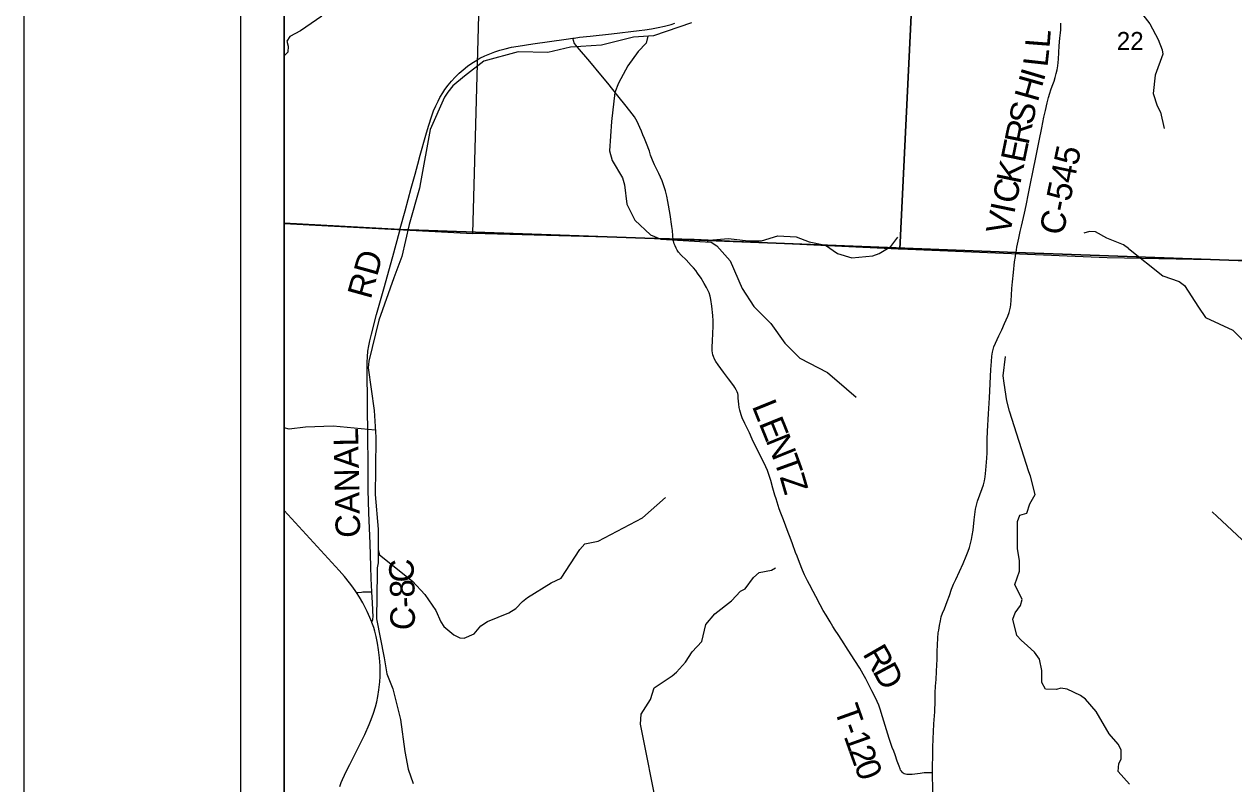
# Model space of a CAD drawing. Extents: x 0 to 34, y 0 to 22.
# Drawn here: x 2 to 4.796, y 15.243 to 16.998 of the extents above; entities that cross this region are included whole.
import ezdxf

# ---------------------------------------------------------------- set-up
doc = ezdxf.new("R2010")
doc.units = 0
for name, color, linetype in [('GM_X_County', 7, 'Continuous'), ('GM_X_County_Road', 7, 'Continuous'), ('GM_X_County_Road_Text', 7, 'Continuous'), ('GM_X_Minor_River', 7, 'Continuous'), ('GM_X_Section', 7, 'Continuous'), ('GM_X_Section_Text', 7, 'Continuous'), ('GM_X_State_Route', 7, 'Continuous'), ('GM_X_Township', 7, 'Continuous'), ('GM_X_Township_Road', 7, 'Continuous'), ('GM_X_Township_Road_Text', 7, 'Continuous'), ('SH_Border', 7, 'Continuous'), ('SH_Data', 7, 'Continuous')]:
    doc.layers.add(name, color=color, linetype=linetype)

msp = doc.modelspace()

# ---------------------------------------------------------------- linework, layer by layer
at = {"layer": 'GM_X_County'}
msp.add_lwpolyline([(7.0736, 21.2003), (2.6013, 21.2003), (2.6013, 14.4003), (9.4013, 14.4003), (9.4013, 21.1598)], dxfattribs=at)
at = {"layer": 'GM_X_County_Road'}
for points in [[(3.2681, 16.9653), (3.271, 16.9657), (3.2838, 16.9674), (3.3083, 16.97), (3.3577, 16.9753), (3.4214, 16.9828), (3.4348, 16.9846), (3.4501, 16.9869), (3.4653, 16.9899), (3.4804, 16.9933), (3.4954, 16.9974), (3.5042, 17.0002)], [(4.2927, 16.4699), (4.2928, 16.4705), (4.2949, 16.4826), (4.2991, 16.5037), (4.3023, 16.5188), (4.3052, 16.5309), (4.3122, 16.5611), (4.3161, 16.5793), (4.3216, 16.6067), (4.3248, 16.6219), (4.3273, 16.634), (4.331, 16.6523), (4.3403, 16.6979), (4.3463, 16.7284), (4.3525, 16.7587), (4.3574, 16.783), (4.3606, 16.7981), (4.3648, 16.8162), (4.3681, 16.8288), (4.3709, 16.8384), (4.3734, 16.8463), (4.3762, 16.8544), (4.3806, 16.8659), (4.3835, 16.8746), (4.3859, 16.8835), (4.3878, 16.8926), (4.3892, 16.9018), (4.3908, 16.9173), (4.3919, 16.9327), (4.3929, 16.9481), (4.3943, 16.9652), (4.3956, 16.9779), (4.3964, 16.9848), (4.3964, 16.994), (4.396, 17.0002)], [(2.8695, 16.5261), (2.8805, 16.5665), (2.8949, 16.6187), (2.9036, 16.6515), (2.91, 16.6745), (2.9157, 16.6949), (2.9283, 16.7411), (2.9345, 16.7621), (2.9421, 16.7858), (2.9464, 16.7975), (2.9512, 16.809), (2.9566, 16.8203), (2.961, 16.8285), (2.9674, 16.8392), (2.9726, 16.847), (2.9801, 16.8569), (2.9881, 16.8665), (2.9966, 16.8756), (3.0055, 16.8843), (3.0148, 16.8926), (3.0246, 16.9005), (3.0347, 16.9077), (3.0426, 16.9127), (3.0535, 16.9189), (3.0647, 16.9244), (3.0761, 16.9293), (3.0877, 16.9338), (3.0996, 16.9377), (3.1116, 16.9409), (3.1268, 16.9443), (3.1421, 16.9471), (3.1759, 16.9522), (3.2528, 16.9632), (3.2681, 16.9653)], [(2.8036, 15.6871), (2.8021, 15.7174), (2.8011, 15.7453), (2.7994, 15.7981), (2.7964, 15.8695), (2.7955, 15.9223), (2.7951, 15.9844), (2.7947, 16.0434), (2.7938, 16.1211), (2.7928, 16.1987), (2.7927, 16.2174), (2.7933, 16.2298), (2.7945, 16.2422), (2.7964, 16.2546), (2.7988, 16.2668), (2.8025, 16.2819), (2.8147, 16.3269), (2.8313, 16.3867), (2.8519, 16.4616), (2.8674, 16.5185), (2.8688, 16.5234), (2.8695, 16.5261)], [(4.1, 15.2685), (4.0999, 15.2892), (4.1002, 15.3016), (4.1008, 15.3264), (4.1014, 15.3481), (4.102, 15.3636), (4.1031, 15.3821), (4.1043, 15.4006), (4.1048, 15.4099), (4.1056, 15.4348), (4.1061, 15.4534), (4.1069, 15.4689), (4.108, 15.4844), (4.1092, 15.5029), (4.1101, 15.5183), (4.1105, 15.5307), (4.1105, 15.54), (4.1105, 15.5493), (4.1109, 15.5647), (4.1118, 15.5801), (4.113, 15.5924), (4.114, 15.5985), (4.1157, 15.6091), (4.1181, 15.6197), (4.1201, 15.6287), (4.1229, 15.6376), (4.1273, 15.6475), (4.1338, 15.6642), (4.1387, 15.6786), (4.1434, 15.6929), (4.1482, 15.7044), (4.1535, 15.7156), (4.1703, 15.7521), (4.1779, 15.769), (4.1824, 15.7806), (4.1854, 15.7894), (4.1879, 15.7984), (4.19, 15.8075), (4.1916, 15.8166), (4.1934, 15.8288), (4.1961, 15.8534), (4.1975, 15.8657), (4.1995, 15.878), (4.2015, 15.8871), (4.2041, 15.896), (4.2093, 15.9107), (4.2146, 15.9253), (4.2174, 15.9341), (4.2196, 15.9431), (4.2211, 15.9523), (4.2227, 15.9676), (4.2251, 15.9954), (4.2258, 16.0078), (4.2261, 16.0202), (4.2263, 16.0389), (4.227, 16.0575), (4.2293, 16.0978), (4.2315, 16.135), (4.2349, 16.2002), (4.2359, 16.2188), (4.2371, 16.2312), (4.2385, 16.2404), (4.24, 16.2464), (4.2418, 16.2523), (4.2454, 16.2609), (4.2531, 16.2779), (4.2597, 16.292), (4.2661, 16.3061), (4.2735, 16.3232), (4.2768, 16.3319), (4.2786, 16.3378), (4.28, 16.3439), (4.2809, 16.35), (4.2817, 16.3593), (4.2822, 16.3717), (4.283, 16.3872), (4.2845, 16.4027), (4.2867, 16.4243), (4.2896, 16.449), (4.2913, 16.4613), (4.2927, 16.4699)], [(2.7683, 15.685), (2.7722, 15.6855), (2.7797, 15.6863), (2.7826, 15.6864), (2.8036, 15.6871)], [(2.8038, 15.6168), (2.8057, 15.6225), (2.8061, 15.6252), (2.8065, 15.6279), (2.8049, 15.6616), (2.8036, 15.6871)], [(4.1243, 14.9987), (4.1248, 14.9996), (4.1258, 15.0026), (4.1261, 15.0056), (4.126, 15.0087), (4.1246, 15.0179), (4.1213, 15.0457), (4.1188, 15.0673), (4.1167, 15.0889), (4.1153, 15.1049), (4.1127, 15.1266), (4.1109, 15.1382), (4.106, 15.1626), (4.1034, 15.1779), (4.1023, 15.1872), (4.1013, 15.2027), (4.1008, 15.2213), (4.1004, 15.24), (4.1, 15.2555), (4.1, 15.2685)]]:
    msp.add_lwpolyline(points, dxfattribs=at)
at = {"layer": 'GM_X_Minor_River'}
for points in [[(4.5595, 17.1163), (4.5776, 17.0849), (4.5859, 17.0193), (4.6019, 16.9985), (4.621, 16.9625), (4.631, 16.9386), (4.6318, 16.9288), (4.6142, 16.8802), (4.6098, 16.8376), (4.6191, 16.8092), (4.6271, 16.7945), (4.6356, 16.7569)], [(2.6882, 17.0164), (2.6391, 16.9821), (2.6137, 16.9692), (2.6069, 16.9585), (2.6104, 16.9468), (2.6093, 16.9335), (2.6013, 16.9244)], [(3.5424, 17.0005), (3.455, 16.971), (3.4084, 16.9675), (3.3349, 16.949), (3.2629, 16.9443), (3.2107, 16.932), (3.1417, 16.934), (3.0626, 16.9122), (3.0176, 16.8779), (2.9911, 16.855), (2.9794, 16.841), (2.9715, 16.8292), (2.9388, 16.7544), (2.9165, 16.6321), (2.9142, 16.6189), (2.8899, 16.535), (2.8731, 16.4609), (2.8547, 16.4119), (2.8197, 16.3143), (2.7966, 16.2198), (2.7955, 16.2043), (2.8087, 16.1057), (2.8127, 16.0442), (2.8118, 15.9703), (2.8116, 15.9118), (2.8179, 15.8311), (2.8186, 15.7537), (2.8163, 15.7419), (2.816, 15.7305), (2.8141, 15.6243), (2.8318, 15.5341), (2.8384, 15.4977), (2.8521, 15.4624), (2.8702, 15.3919), (2.8803, 15.318), (2.8876, 15.2774), (2.8991, 15.2441)], [(3.4416, 16.97), (3.438, 16.9539), (3.4195, 16.9345), (3.3953, 16.9018), (3.3735, 16.8615), (3.3652, 16.8399), (3.3578, 16.7727), (3.3528, 16.7052), (3.3589, 16.6832), (3.3833, 16.6427), (3.3879, 16.6268), (3.3933, 16.5824), (3.4113, 16.5449), (3.4478, 16.5109), (3.472, 16.5015), (3.588, 16.4943), (3.6013, 16.486), (3.6317, 16.4512), (3.66, 16.3871), (3.6866, 16.3459), (3.7258, 16.3062), (3.7585, 16.2607), (3.7928, 16.2263), (3.8569, 16.1932), (3.9006, 16.1554), (3.923, 16.1365)], [(3.579, 16.4948), (3.5823, 16.4988), (3.6282, 16.5027), (3.6736, 16.4976), (3.7047, 16.4977), (3.7418, 16.5088), (3.7843, 16.5066), (3.8146, 16.495), (3.8525, 16.4875), (3.8803, 16.4682), (3.9129, 16.4581), (3.9614, 16.4624), (3.9765, 16.4682), (4.0037, 16.4846), (4.0196, 16.5058)], [(4.5528, 16.4798), (4.5411, 16.4885), (4.5024, 16.5039), (4.4762, 16.5179), (4.4629, 16.519), (4.4497, 16.5151)], [(4.5528, 16.4798), (4.6319, 16.4163), (4.6702, 16.4031), (4.682, 16.3945), (4.7149, 16.3445), (4.7309, 16.3203), (4.7939, 16.291), (4.8248, 16.2604), (4.8466, 16.2184), (4.861, 16.2086), (4.8857, 16.2011), (4.9465, 16.1737), (4.9669, 16.1764), (4.9973, 16.1637), (5.0125, 16.1512), (5.0372, 16.138), (5.0721, 16.1306), (5.1199, 16.1343)], [(4.555, 15.2428), (4.5288, 15.2716), (4.5302, 15.2905), (4.5355, 15.3004), (4.5358, 15.3216), (4.529, 15.3353), (4.5084, 15.3587), (4.4779, 15.4102), (4.4532, 15.4386), (4.4418, 15.4473), (4.4111, 15.4616), (4.3963, 15.4639), (4.3864, 15.4612), (4.361, 15.4622), (4.3523, 15.4774), (4.3522, 15.5047), (4.3468, 15.5312), (4.3357, 15.5471), (4.3194, 15.5619), (4.3046, 15.5751), (4.2947, 15.5857), (4.2851, 15.6236), (4.2907, 15.6384), (4.3028, 15.6551), (4.3073, 15.6692), (4.2901, 15.7036), (4.3006, 15.7348), (4.3006, 15.7594), (4.2959, 15.7864), (4.2965, 15.849), (4.3017, 15.8641), (4.318, 15.8684), (4.3244, 15.89), (4.3372, 15.9117), (4.3261, 15.9541), (4.3222, 15.964), (4.2778, 16.1038), (4.2713, 16.1277), (4.2655, 16.1686), (4.2632, 16.1857), (4.2683, 16.2301)], [(2.8116, 16.0601), (2.7141, 16.069), (2.65, 16.0669), (2.6125, 16.0626), (2.6013, 16.0656)], [(2.8183, 15.7837), (2.8215, 15.7723), (2.8979, 15.7114), (2.9264, 15.6804), (2.9516, 15.6433), (2.963, 15.6176), (2.9702, 15.6066), (2.9934, 15.5877), (3.0067, 15.5805), (3.0173, 15.5794), (3.04, 15.5901), (3.0555, 15.608), (3.071, 15.6179), (3.1202, 15.6385), (3.1368, 15.6481), (3.1519, 15.6641), (3.1633, 15.6736), (3.2181, 15.7079), (3.2412, 15.7182), (3.2842, 15.7843), (3.2959, 15.7973), (3.3269, 15.8035), (3.4294, 15.8573), (3.4823, 15.9048)], [(5.0759, 15.5103), (5.0739, 15.5171), (5.0628, 15.5292), (5.0407, 15.564), (4.9965, 15.612), (4.9273, 15.6497), (4.9063, 15.675), (4.8891, 15.7098), (4.8529, 15.7651), (4.8151, 15.8078), (4.7577, 15.8606), (4.7462, 15.8712)], [(3.4562, 15.2227), (3.4342, 15.3349), (3.4246, 15.3812), (3.426, 15.4039), (3.4475, 15.4381), (3.4561, 15.4647), (3.4981, 15.4929), (3.5079, 15.5009), (3.5287, 15.5245), (3.5441, 15.5481), (3.5664, 15.5717), (3.5754, 15.6111), (3.5969, 15.6359), (3.6347, 15.6663), (3.6558, 15.6884), (3.6664, 15.6934), (3.6861, 15.7196), (3.6993, 15.7314), (3.7273, 15.7368), (3.7371, 15.7418)]]:
    msp.add_lwpolyline(points, dxfattribs=at)
at = {"layer": 'GM_X_Section'}
msp.add_line((2.6013, 17.5659), (2.6013, 16.5373), dxfattribs=at)
msp.add_lwpolyline([(2.6013, 16.5373), (3.0372, 16.514), (3.0654, 17.5504), (2.6013, 17.5659)], dxfattribs=at)
for points in [[(3.0654, 17.5504), (4.0746, 17.5111), (4.0244, 16.4784), (4.0204, 16.4785), (3.5484, 16.5002), (3.0372, 16.514)], [(4.0746, 17.5111), (5.0805, 17.4591), (5.0528, 16.4469), (4.8222, 16.4519), (4.5034, 16.4581), (4.0244, 16.4784)]]:
    msp.add_lwpolyline(points, close=True, dxfattribs=at)
at = {"layer": 'GM_X_State_Route'}
msp.add_lwpolyline([(2.7297, 15.2375), (2.7331, 15.2464), (2.7359, 15.2532), (2.7451, 15.273), (2.7528, 15.288), (2.7793, 15.3407), (2.7876, 15.3574), (2.7977, 15.3801), (2.8024, 15.3916), (2.8076, 15.4062), (2.8121, 15.421), (2.8152, 15.433), (2.8177, 15.4451), (2.8201, 15.4605), (2.8221, 15.4789), (2.8227, 15.4915), (2.8229, 15.5037), (2.8227, 15.5159), (2.8214, 15.5346), (2.8192, 15.5531), (2.8167, 15.5684), (2.8138, 15.5836), (2.8109, 15.5957), (2.8083, 15.6046), (2.804, 15.6162), (2.8038, 15.6168), (2.7992, 15.6276), (2.7925, 15.6416), (2.7826, 15.661), (2.775, 15.6745), (2.7683, 15.685), (2.7667, 15.6876), (2.7597, 15.6978), (2.7523, 15.7078), (2.7406, 15.7222), (2.7284, 15.7364), (2.6013, 15.8744)], dxfattribs=at)
at = {"layer": 'GM_X_Township'}
for points in [[(6.2234, 21.2003), (2.6013, 21.2003), (2.6013, 16.5379)], [(2.6013, 16.5379), (2.8688, 16.5234), (3.5006, 16.5009), (4.2928, 16.4705), (5.2983, 16.434), (6.0664, 16.4042), (6.0778, 16.7443), (6.0911, 17.2548), (6.11, 17.7459), (6.1473, 18.845), (6.1717, 19.6397), (6.1731, 19.6616), (6.1731, 19.6818), (6.1733, 19.6859), (6.2234, 21.2003)], [(2.6013, 16.5379), (2.6013, 14.4003), (6.0009, 14.4003)], [(5.2983, 16.434), (4.2928, 16.4705), (3.5006, 16.5009), (2.8688, 16.5234), (2.6013, 16.5379)]]:
    msp.add_lwpolyline(points, dxfattribs=at)
at = {"layer": 'GM_X_Township_Road'}
for points in [[(3.4997, 16.5072), (3.4995, 16.5088), (3.4986, 16.5212), (3.4975, 16.5304), (3.493, 16.558), (3.4879, 16.5886), (3.4852, 16.6007), (3.4822, 16.6128), (3.4788, 16.6246), (3.4746, 16.6362), (3.471, 16.6448), (3.4671, 16.6532), (3.46, 16.667), (3.4573, 16.6726), (3.4547, 16.6782), (3.4522, 16.6839), (3.4479, 16.6955), (3.4453, 16.7044), (3.4389, 16.7219), (3.4341, 16.7334), (3.4304, 16.7419), (3.4268, 16.7505), (3.4231, 16.7589), (3.4168, 16.773), (3.4139, 16.7784), (3.4106, 16.7836), (3.4051, 16.791), (3.3918, 16.8082), (3.3725, 16.8325), (3.3489, 16.8614), (3.3331, 16.8806), (3.3072, 16.9116), (3.2788, 16.9446), (3.2749, 16.9495), (3.2732, 16.952), (3.2716, 16.9547), (3.2704, 16.9575), (3.2681, 16.9653)], [(4.1, 15.2685), (4.0917, 15.2691), (4.0891, 15.2691), (4.0863, 15.2691), (4.0804, 15.2687), (4.0712, 15.2675), (4.065, 15.2667), (4.0527, 15.2651), (4.0496, 15.2648), (4.0436, 15.2646), (4.0405, 15.2648), (4.0374, 15.2655), (4.0346, 15.2666), (4.0319, 15.2682), (4.0296, 15.2703), (4.0277, 15.2726), (4.026, 15.2752), (4.0246, 15.278), (4.0223, 15.2838), (4.0181, 15.2954), (4.0131, 15.31), (4.01, 15.3187), (4.0067, 15.3275), (4.0036, 15.3362), (3.9996, 15.348), (3.9844, 15.3983), (3.9788, 15.416), (3.9757, 15.4248), (3.972, 15.4333), (3.9678, 15.4416), (3.9591, 15.4581), (3.9509, 15.4749), (3.9454, 15.486), (3.9394, 15.4969), (3.9315, 15.5102), (3.9198, 15.5285), (3.9047, 15.5518), (3.8902, 15.5749), (3.8813, 15.5882), (3.8745, 15.5985), (3.8696, 15.6064), (3.8633, 15.6171), (3.8538, 15.633), (3.8473, 15.6435), (3.8397, 15.6571), (3.8297, 15.6763), (3.8239, 15.6873), (3.8152, 15.7036), (3.8109, 15.7119), (3.804, 15.7258), (3.7989, 15.7371), (3.7921, 15.7544), (3.7867, 15.7689), (3.7833, 15.7774), (3.7757, 15.7976), (3.7703, 15.8121), (3.766, 15.8238), (3.7553, 15.8529), (3.7494, 15.8685), (3.7451, 15.8788), (3.7427, 15.8863), (3.738, 15.9014), (3.7353, 15.9097), (3.7309, 15.9261), (3.7259, 15.944), (3.7238, 15.9505), (3.7208, 15.9598), (3.718, 15.9673), (3.7143, 15.9758), (3.7077, 15.9898), (3.6978, 16.0091), (3.683, 16.0397), (3.6765, 16.0537), (3.6657, 16.0759), (3.6597, 16.0888), (3.6572, 16.0956), (3.6556, 16.1006), (3.6542, 16.1066), (3.6531, 16.1126), (3.6521, 16.1205), (3.6508, 16.1344), (3.6502, 16.1413), (3.6494, 16.145), (3.6478, 16.1489), (3.6456, 16.1535), (3.6428, 16.1583), (3.6404, 16.1622), (3.6374, 16.1663), (3.6334, 16.1719), (3.628, 16.1789), (3.6168, 16.1937), (3.6039, 16.2113), (3.5987, 16.219), (3.5957, 16.2244), (3.5932, 16.2301), (3.592, 16.2344), (3.5912, 16.2386), (3.5906, 16.2434), (3.5903, 16.2495), (3.5908, 16.2685), (3.5917, 16.2813), (3.5927, 16.3028), (3.5926, 16.3124), (3.592, 16.3253), (3.5898, 16.3466), (3.5875, 16.3619), (3.5857, 16.3698), (3.5834, 16.3772), (3.5806, 16.3835), (3.5772, 16.3898), (3.5717, 16.3992), (3.5646, 16.411), (3.5567, 16.4225), (3.5524, 16.4285), (3.5471, 16.4347), (3.542, 16.4405), (3.5301, 16.4533), (3.5187, 16.4646), (3.5127, 16.4714), (3.5093, 16.476), (3.5068, 16.4806), (3.5045, 16.4859), (3.5027, 16.4906), (3.5012, 16.4973), (3.5006, 16.5009), (3.4997, 16.5072)]]:
    msp.add_lwpolyline(points, dxfattribs=at)
at = {"layer": 'SH_Border'}
msp.add_lwpolyline([(2, 21.5), (33.5, 21.5), (33.5, 0.5), (2, 0.5)], close=True, dxfattribs=at)
at = {"layer": 'SH_Data'}
for p, q in [((2.5, 21.2997), (2.5, 14.2997)), ((2.6, 21.1997), (2.6, 14.3997))]:
    msp.add_line(p, q, dxfattribs=at)

# ---------------------------------------------------------------- texts
at = {"layer": 'GM_X_County_Road_Text'}
for s, height, rotation, p in [('L', 0.0568, 85.6795, (4.3702, 16.9417)), ('L', 0.0568, 83.6962, (4.3653, 16.8974)), ('I', 0.0568, 73.3673, (4.3564, 16.864)), ('H', 0.0568, 74.2708, (4.3429, 16.8161)), ('S', 0.0568, 77.514, (4.3306, 16.7626)), ('R', 0.0568, 78.292, (4.3212, 16.7171)), ('E', 0.0568, 78.3626, (4.3126, 16.6755)), ('C-545', 0.05682, 78.2647, (4.4017, 16.5078)), ('K', 0.0568, 78.3579, (4.3025, 16.6265)), ('C', 0.0568, 78.3599, (4.2931, 16.5808)), ('I', 0.0568, 78.3594, (4.2884, 16.5579)), ('V', 0.0568, 78.3614, (4.2783, 16.5089)), ('RD', 0.05682, 74.5318, (2.801, 16.3605)), ('CANAL', 0.05682, 91.1944, (2.777, 15.812)), ('C', 0.0568, 92.2409, (2.9016, 15.7094)), ('8', 0.0568, 92.8216, (2.9033, 15.6746)), ('-', 0.0568, 93.3817, (2.9047, 15.6515)), ('C', 0.0568, 84.9978, (2.9005, 15.5959))]:
    msp.add_text(s, height=height, rotation=rotation, dxfattribs=at).set_placement(p)
at = {"layer": 'GM_X_Section_Text'}
msp.add_text('22', height=0.04186, rotation=0, dxfattribs=at).set_placement((4.5256, 16.9379))
at = {"layer": 'GM_X_Township_Road_Text'}
for s, rotation, p in [('L', 292.0354, (3.6815, 16.1158)), ('E', 292.0375, (3.6975, 16.0764)), ('N', 291.9841, (3.7134, 16.0371)), ('T', 289.8974, (3.7319, 15.9912)), ('Z', 286.3204, (3.7461, 15.9521)), ('R', 299.9322, (3.9371, 15.5437)), ('D', 298.1552, (3.9602, 15.5036)), ('T', 289.5558, (3.8719, 15.4154)), ('-', 289.5483, (3.8862, 15.3753)), ('1', 289.5881, (3.894, 15.3533)), ('2', 289.7607, (3.9058, 15.3201)), ('0', 290.3811, (3.9178, 15.2866))]:
    msp.add_text(s, height=0.0568, rotation=rotation, dxfattribs=at).set_placement(p)

doc.saveas('drawing.dxf')
